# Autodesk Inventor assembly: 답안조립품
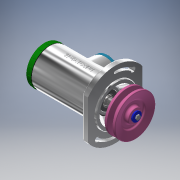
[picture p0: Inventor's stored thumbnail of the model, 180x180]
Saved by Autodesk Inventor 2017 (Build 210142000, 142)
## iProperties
Part Number: 답안조립품
Material: 일반
Document SubType Name: Assembly
Designer: MRC
Author: MRC
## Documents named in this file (22)
- C:\Users\MRC\Desktop\720506V1006\답안조립품.iam
- C:\Users\MRC\Desktop\720506V1006\축.ipt
- C:\Users\MRC\Desktop\720506V1006\베어링 6202.ipt
- C:\Users\MRC\Desktop\720506V1006\부시1.ipt
- C:\Users\MRC\Desktop\720506V1006\멈춤링 35 x 1.6.ipt
- C:\Users\MRC\Desktop\720506V1006\멈춤링 15 x 1.ipt
- C:\Users\MRC\Desktop\720506V1006\부시2.ipt
- C:\Users\MRC\Desktop\720506V1006\와셔 10 x 21.ipt
- C:\Users\MRC\Desktop\720506V1006\너트 M10.ipt
- C:\Users\MRC\Desktop\720506V1006\본체.ipt
- C:\Users\MRC\Desktop\720506V1006\개스킷.ipt
- C:\Users\MRC\Desktop\720506V1006\사이드 커버.ipt
- 사이드 커버.ipt
- C:\Users\MRC\Desktop\720506V1006\탑 커버.ipt
- C:\Users\MRC\Desktop\720506V1006\와셔 3 x 6.ipt
- C:\Users\MRC\Desktop\720506V1006\십자볼트 M3 x 10.ipt
- C:\Users\MRC\Desktop\720506V1006\오일 실 15 x 30 x 7.ipt
- C:\Users\MRC\Desktop\720506V1006\키 4 x 4.ipt
- C:\Users\MRC\Desktop\720506V1006\V-벨트풀리.ipt
- C:\Users\MRC\Desktop\720506V1006\와셔 4 x 16.ipt
- C:\Users\MRC\Desktop\720506V1006\볼트 M4 x 10.ipt
- C:\Users\MRC\Desktop\720506V1006\멈춤나사 M3.ipt
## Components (3 placed, 3 different names)
1. 개스킷:1
2. V-벨트풀리:1 — 플러쉬:3
3. ISO 4017 M4 x 10:1
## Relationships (1: Flush 1)
- 플러쉬:3 [Flush]: V-벨트풀리:1
